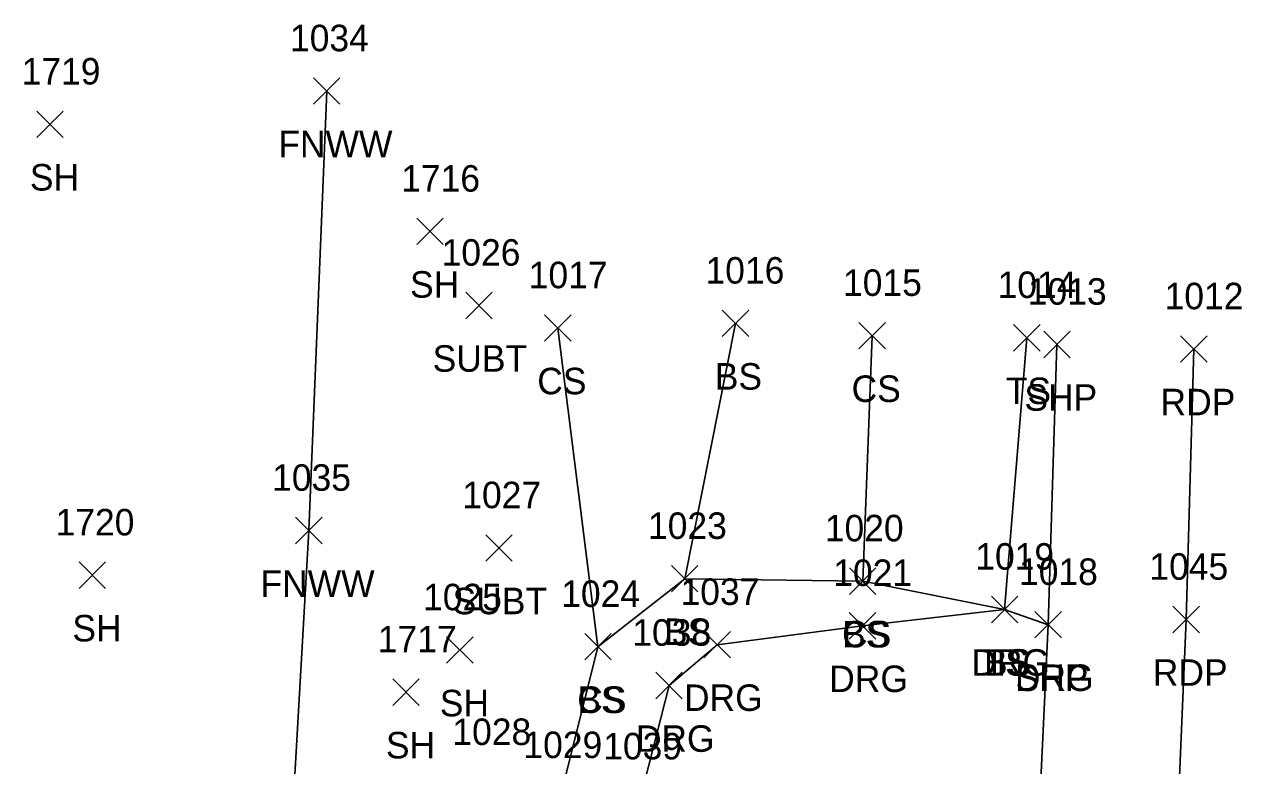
# Model space of a CAD drawing. Extents: x 1443960 to 1446865, y 610387 to 616706.
# Drawn here: x 1446519 to 1446610.9, y 611422.5 to 611478.4 of the extents above; entities that cross this region are included whole.
import ezdxf

# ---------------------------------------------------------------- set-up
doc = ezdxf.new("R2010")
doc.units = 0
for name, color, linetype in [('L_A', 7, 'Continuous'), ('L_I', 7, 'Continuous'), ('L_TIC', 7, 'Continuous'), ('LELB', 7, 'Continuous'), ('LFNC', 7, 'Continuous'), ('P_A', 7, 'Continuous'), ('P_I', 7, 'Continuous'), ('P_TIC', 7, 'Continuous'), ('PET', 7, 'Continuous'), ('PSP', 7, 'Continuous'), ('R_A', 7, 'Continuous'), ('R_I', 7, 'Continuous'), ('R_TIC', 7, 'Continuous'), ('RDG', 7, 'Continuous'), ('U_A', 7, 'Continuous'), ('U_I', 7, 'Continuous'), ('U_TIC', 7, 'Continuous')]:
    doc.layers.add(name, color=color, linetype=linetype)

msp = doc.modelspace()

# ---------------------------------------------------------------- linework, layer by layer
at = {"layer": 'L_TIC'}
for points in [[(1446540.826, 611472.4), (1446542.826, 611474.4)], [(1446542.826, 611472.4), (1446540.826, 611474.4)], [(1446519.941, 611469.892), (1446521.941, 611471.892)], [(1446521.941, 611469.892), (1446519.941, 611471.892)], [(1446548.623, 611461.81), (1446550.623, 611463.81)], [(1446550.623, 611461.81), (1446548.623, 611463.81)], [(1446558.271, 611454.522), (1446560.271, 611456.522)], [(1446560.271, 611454.522), (1446558.271, 611456.522)], [(1446571.667, 611454.871), (1446573.667, 611456.871)], [(1446573.667, 611454.871), (1446571.667, 611456.871)], [(1446581.986, 611453.943), (1446583.986, 611455.943)], [(1446583.986, 611453.943), (1446581.986, 611455.943)], [(1446593.651, 611453.784), (1446595.651, 611455.784)], [(1446595.651, 611453.784), (1446593.651, 611455.784)], [(1446539.478, 611439.241), (1446541.478, 611441.241)], [(1446541.478, 611439.241), (1446539.478, 611441.241)], [(1446523.146, 611435.875), (1446525.146, 611437.875)], [(1446525.146, 611435.875), (1446523.146, 611437.875)], [(1446567.838, 611435.61), (1446569.838, 611437.61)], [(1446569.838, 611435.61), (1446567.838, 611437.61)], [(1446567.838, 611435.61), (1446569.838, 611437.61)], [(1446569.838, 611435.61), (1446567.838, 611437.61)], [(1446581.267, 611435.427), (1446583.267, 611437.427)], [(1446583.267, 611435.427), (1446581.267, 611437.427)], [(1446581.267, 611435.427), (1446583.267, 611437.427)], [(1446583.267, 611435.427), (1446581.267, 611437.427)], [(1446591.974, 611433.291), (1446593.974, 611435.291)], [(1446593.974, 611433.291), (1446591.974, 611435.291)], [(1446591.974, 611433.291), (1446593.974, 611435.291)], [(1446593.974, 611433.291), (1446591.974, 611435.291)], [(1446550.87, 611430.226), (1446552.87, 611432.226)], [(1446552.87, 611430.226), (1446550.87, 611432.226)], [(1446561.29, 611430.479), (1446563.29, 611432.479)], [(1446563.29, 611430.479), (1446561.29, 611432.479)], [(1446561.29, 611430.479), (1446563.29, 611432.479)], [(1446563.29, 611430.479), (1446561.29, 611432.479)], [(1446546.804, 611427.052), (1446548.804, 611429.052)], [(1446548.804, 611427.052), (1446546.804, 611429.052)]]:
    msp.add_lwpolyline(points, dxfattribs=at)
at = {"layer": 'LELB'}
for points in [[(1446559.271, 611455.522), (1446562.29, 611431.479)], [(1446572.667, 611455.871), (1446568.838, 611436.61)], [(1446582.986, 611454.943), (1446582.267, 611436.427)], [(1446594.651, 611454.784), (1446592.974, 611434.291)], [(1446592.974, 611434.291), (1446582.267, 611436.427), (1446568.838, 611436.61), (1446562.29, 611431.479), (1446559.446, 611420.077), (1446558.014, 611403.6), (1446565.138, 611400.157), (1446577.92, 611397.125), (1446591.907, 611396.618)]]:
    msp.add_lwpolyline(points, dxfattribs=at)
at = {"layer": 'LFNC'}
msp.add_lwpolyline([(1446541.826, 611473.4), (1446540.478, 611440.241), (1446538.491, 611405.547), (1446538.432, 611402.845), (1446538.347, 611399.913), (1446537.932, 611395.113), (1446537.659, 611371.171), (1446537.105, 611347.559)], dxfattribs=at)
at = {"layer": 'P_TIC'}
for points in [[(1446595.928, 611453.28), (1446597.928, 611455.28)], [(1446597.928, 611453.28), (1446595.928, 611455.28)], [(1446606.251, 611452.936), (1446608.251, 611454.936)], [(1446608.251, 611452.936), (1446606.251, 611454.936)], [(1446595.266, 611432.138), (1446597.266, 611434.138)], [(1446597.266, 611432.138), (1446595.266, 611434.138)], [(1446605.67, 611432.533), (1446607.67, 611434.533)], [(1446607.67, 611432.533), (1446605.67, 611434.533)]]:
    msp.add_lwpolyline(points, dxfattribs=at)
at = {"layer": 'PET'}
msp.add_lwpolyline([(1446607.251, 611453.936), (1446606.67, 611433.533), (1446604.975, 611393.161), (1446602.224, 611344.384), (1446599.364, 611301.149), (1446596.111, 611259.063), (1446592.204, 611211.242), (1446588.27, 611166.355), (1446587.47, 611154.323)], dxfattribs=at)
at = {"layer": 'PSP'}
msp.add_lwpolyline([(1446596.928, 611454.28), (1446596.266, 611433.138), (1446594.493, 611395.965), (1446591.306, 611343.168)], dxfattribs=at)
at = {"layer": 'R_TIC'}
for points in [[(1446591.974, 611433.291), (1446593.974, 611435.291)], [(1446593.974, 611433.291), (1446591.974, 611435.291)], [(1446595.266, 611432.138), (1446597.266, 611434.138)], [(1446597.266, 611432.138), (1446595.266, 611434.138)], [(1446581.25, 611432.059), (1446583.25, 611434.059)], [(1446583.25, 611432.059), (1446581.25, 611434.059)], [(1446570.293, 611430.633), (1446572.293, 611432.633)], [(1446572.293, 611430.633), (1446570.293, 611432.633)], [(1446566.654, 611427.55), (1446568.654, 611429.55)], [(1446568.654, 611427.55), (1446566.654, 611429.55)]]:
    msp.add_lwpolyline(points, dxfattribs=at)
at = {"layer": 'RDG'}
msp.add_lwpolyline([(1446596.266, 611433.138), (1446592.974, 611434.291), (1446582.25, 611433.059), (1446571.293, 611431.633), (1446567.654, 611428.55), (1446565.469, 611419.978), (1446564.196, 611405.657), (1446579.567, 611401.306), (1446591.907, 611396.618), (1446594.493, 611395.965)], dxfattribs=at)
at = {"layer": 'U_TIC'}
for points in [[(1446552.322, 611456.224), (1446554.322, 611458.224)], [(1446554.322, 611456.224), (1446552.322, 611458.224)], [(1446553.826, 611437.929), (1446555.826, 611439.929)], [(1446555.826, 611437.929), (1446553.826, 611439.929)]]:
    msp.add_lwpolyline(points, dxfattribs=at)

# ---------------------------------------------------------------- texts
at = {"layer": 'L_A'}
for s, p in [('FNWW', (1446538.172, 611468.4)), ('SH', (1446519.429, 611465.892)), ('SH', (1446548.111, 611457.81)), ('CS', (1446557.712, 611450.522)), ('BS', (1446571.108, 611450.871)), ('CS', (1446581.427, 611449.943)), ('TS', (1446593.06, 611449.784)), ('FNWW', (1446536.825, 611435.241)), ('SH', (1446522.634, 611431.875)), ('BS', (1446567.279, 611431.61)), ('BS', (1446567.279, 611431.61)), ('CS', (1446580.708, 611431.427)), ('BS', (1446580.708, 611431.427)), ('TS', (1446591.383, 611429.291)), ('BS', (1446591.415, 611429.291)), ('SH', (1446550.359, 611426.226)), ('CS', (1446560.731, 611426.479)), ('BS', (1446560.731, 611426.479)), ('SH', (1446546.292, 611423.052))]:
    msp.add_text(s, height=2, dxfattribs=at).set_placement(p)
at = {"layer": 'L_I'}
for s, p in [('1034', (1446539.054, 611476.4)), ('1719', (1446518.807, 611473.892)), ('1716', (1446547.442, 611465.81)), ('1016', (1446570.407, 611458.871)), ('1017', (1446557.067, 611458.522)), ('1015', (1446580.782, 611457.943)), ('1014', (1446592.446, 611457.784)), ('1035', (1446537.707, 611443.241)), ('1720', (1446521.366, 611439.875)), ('1023', (1446566.067, 611439.61)), ('1023', (1446566.067, 611439.61)), ('1020', (1446579.409, 611439.427)), ('1020', (1446579.409, 611439.427)), ('1019', (1446590.762, 611437.291)), ('1019', (1446590.762, 611437.291)), ('1025', (1446549.099, 611434.226)), ('1024', (1446559.519, 611434.479)), ('1024', (1446559.519, 611434.479)), ('1717', (1446545.678, 611431.052)), ('1029', (1446556.667, 611423.077))]:
    msp.add_text(s, height=2, dxfattribs=at).set_placement(p)
at = {"layer": 'P_A'}
for s, p in [('SHP', (1446594.464, 611449.28)), ('RDP', (1446604.739, 611448.936)), ('RDP', (1446604.158, 611428.533)), ('SHP', (1446593.802, 611428.138))]:
    msp.add_text(s, height=2, dxfattribs=at).set_placement(p)
at = {"layer": 'P_I'}
for s, p in [('1013', (1446594.724, 611457.28)), ('1012', (1446605.046, 611456.936)), ('1018', (1446594.062, 611436.138)), ('1045', (1446603.899, 611436.533))]:
    msp.add_text(s, height=2, dxfattribs=at).set_placement(p)
at = {"layer": 'R_A'}
for p in [(1446590.462, 611429.291), (1446579.738, 611428.059), (1446593.755, 611428.138), (1446568.781, 611426.633), (1446565.143, 611423.55)]:
    msp.add_text('DRG', height=2, dxfattribs=at).set_placement(p)
at = {"layer": 'R_I'}
for s, p in [('1019', (1446590.762, 611437.291)), ('1021', (1446580.045, 611436.059)), ('1018', (1446594.062, 611436.138)), ('1037', (1446568.522, 611434.633)), ('1038', (1446564.883, 611431.55)), ('1039', (1446562.69, 611422.978))]:
    msp.add_text(s, height=2, dxfattribs=at).set_placement(p)
at = {"layer": 'U_A'}
for p in [(1446549.818, 611452.224), (1446551.322, 611433.929)]:
    msp.add_text('SUBT', height=2, dxfattribs=at).set_placement(p)
at = {"layer": 'U_I'}
for s, p in [('1026', (1446550.495, 611460.224)), ('1027', (1446552.054, 611441.929)), ('1028', (1446551.308, 611424.063))]:
    msp.add_text(s, height=2, dxfattribs=at).set_placement(p)

doc.saveas('drawing.dxf')
